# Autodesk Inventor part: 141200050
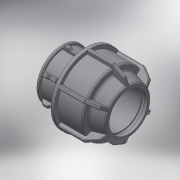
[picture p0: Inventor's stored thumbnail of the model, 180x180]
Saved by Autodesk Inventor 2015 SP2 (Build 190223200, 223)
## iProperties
Created: 2017-08
Part Number: 141200050
Material: Generic
Description: PLASSON L.14 END PLUG (SILVER) 50
Document SubType Name: Modeling
Designer: KIM
Density: 1 g/cm^3
Appearance: Default
Author: KIM
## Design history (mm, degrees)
derived "141200.ipt"
feature "Solid1::141200.ipt"
tag "TaggingFeature1"
body "Solid1"
other parameters: "d4" = 15 deg, "d5" = 46.86, "d6" = 15.4638, "d10" = 92, "d16" = 51, "d17" = 3.55, "d18" = 93, "d24" = 3.55, "d25" = 82.8, "d26" = 69, "d27" = 3.55, "d28" = 135 deg, "d29" = 2.13, "d31" = 2.5, "d44" = 1, "d46" = 150 deg, "d49" = 4.6, "d50" = 0, "d51" = 2.76, "d52" = 1.84, "d53" = 45 deg, "d54" = 18.6, "d55" = 7.44, "d56" = 4.6, "d57" = 0, "d58" = 1.5, "d59" = 1, "d61" = 360 deg, "d66" = 65, "d68" = 71, "d69" = 2.79, "E_" = 92, "H_" = 93, "l_" = 71
